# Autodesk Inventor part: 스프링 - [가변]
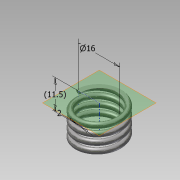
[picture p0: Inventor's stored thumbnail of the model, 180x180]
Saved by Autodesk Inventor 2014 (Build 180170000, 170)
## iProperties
Created: 2015-04
Part Number: 스프링 - [가변]
Material: 강철, 탄소
Document SubType Name: Modeling
Designer: Administrator
Density: 7.87 g/cm^3
Appearance: 반연마
Mass: 4.78745 g
Surface Area: 12.524 cm^2
Volume: 0.608316 cm^3
Author: Administrator
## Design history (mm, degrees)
sketch "스케치1"
  geometry: L1 (0, 0)-(-8, 0); L2 (-8, 0)-(-8, 11.5); L3 (-8, 11.5)-(0, 11.5); L4 (0, 11.5)-(0, 0); C1 r 1 at (-8, 0)
  constraints: 8 end point, 2 parallel, 1 centre point, 1 coincident, 1 horizontal, 1 perpendicular
  dimensions: "d0" = 16 diameter of L2 L4; "d1" = 11.50049 distance between parallel lines of L1 L3 (derived); "d2" = 2 diameter of C1
feature "코일1" pitch "d3" = 10; turns "d5" = 4; dims "d4" = 11.50049 (= d1), "d6" = 0, angle "d7" = 90 deg, angle "d8" = 90 deg, "d9" = 0, "d10" = 0
sketch "스케치2"
  geometry: L1 (9, 0)-(7, 0) reference; 1 further point
  constraints: 1 horizontal alignment
extrude "돌출1" cut sketch "스케치2" stored distance "d11" = 10; taper "d12" = 0 deg
node "작업 평면1"
sketch "스케치3"
  geometry: L1 (-9, 0)-(-7, 0) reference; 1 further point
  constraints: 1 horizontal alignment
extrude "돌출2" cut sketch "스케치3" stored distance "d13" = 10; taper "d14" = 0 deg
node "솔리드1"
node "절단 모서리 투영1"
node "절단 모서리 투영2"
